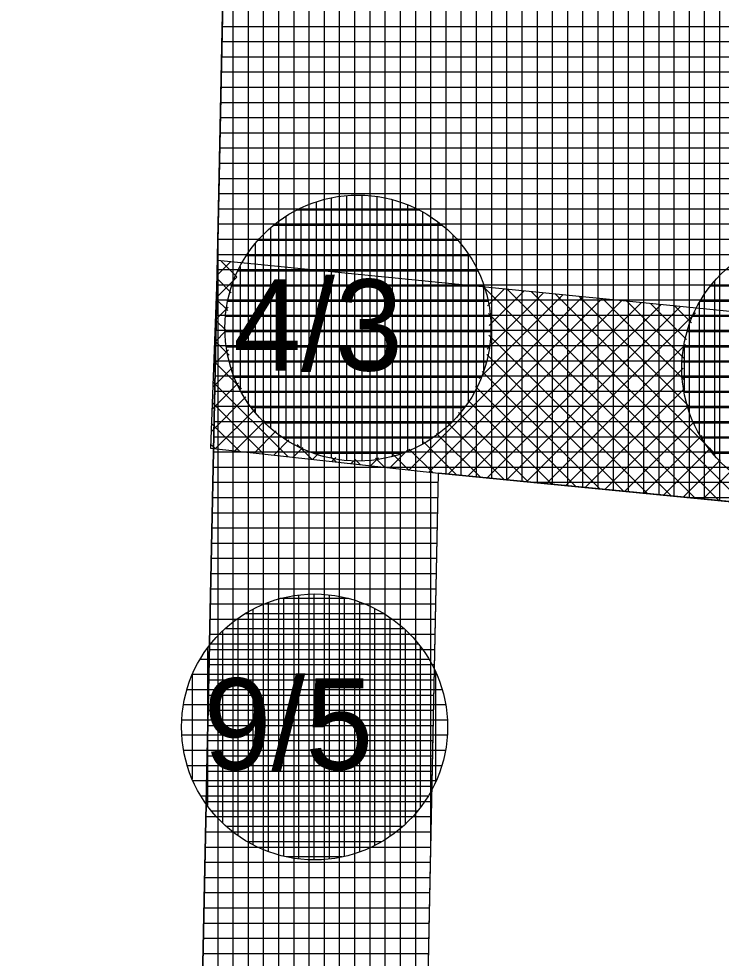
# Model space of a CAD drawing. Extents: x -566461 to -565198, y -1096301 to -1095707.
# Drawn here: x -565645.08 to -565635.84, y -1095892.27 to -1095879.91 of the extents above; entities that cross this region are included whole.
import ezdxf

# ---------------------------------------------------------------- set-up
doc = ezdxf.new("R2010")
doc.units = 0
for name, color, linetype in [('Vrstva 1', 7, 'Continuous'), ('Vrstva 40', 7, 'Continuous'), ('Vrstva 41', 7, 'Continuous'), ('Vrstva 42', 7, 'Continuous'), ('Vrstva 43', 7, 'Continuous'), ('Vrstva 44', 7, 'Continuous')]:
    doc.layers.add(name, color=color, linetype=linetype)

msp = doc.modelspace()

# ---------------------------------------------------------------- linework, layer by layer
at = {"layer": 'Vrstva 1'}
for p, q in [((-565642.52, -1095885.6), (-565642.21, -1095870.56)), ((-565645.08, -1096008.78), (-565642.52, -1095885.6)), ((-565642.11, -1096010.51), (-565639.56, -1095885.89)), ((-565630.78, -1095886.75), (-565639.56, -1095885.89))]:
    msp.add_line(p, q, dxfattribs=at)
at = {"layer": 'Vrstva 41'}
for p, q in [((-565642.475, -1095883.288), (-565642.297, -1095883.11)), ((-565642.212, -1095883.306), (-565642.42, -1095883.098)), ((-565642.486, -1095883.582), (-565642.214, -1095883.309)), ((-565642.285, -1095883.516), (-565642.477, -1095883.324)), ((-565638.97, -1095883.46), (-565638.953, -1095883.443)), ((-565636.186, -1095886.22), (-565638.965, -1095883.442)), ((-565639.944, -1095885.848), (-565637.667, -1095883.571)), ((-565639.024, -1095884.645), (-565637.924, -1095883.545)), ((-565638.918, -1095884.257), (-565638.182, -1095883.52)), ((-565638.916, -1095883.689), (-565638.696, -1095883.469)), ((-565638.892, -1095883.947), (-565638.439, -1095883.494)), ((-565635.873, -1095886.251), (-565638.651, -1095883.473)), ((-565635.559, -1095886.282), (-565638.337, -1095883.504)), ((-565635.93, -1095885.628), (-565638.023, -1095883.536)), ((-565636.267, -1095885.009), (-565637.708, -1095883.567)), ((-565642.497, -1095883.876), (-565642.326, -1095883.705)), ((-565642.333, -1095883.75), (-565642.487, -1095883.597)), ((-565639.689, -1095885.876), (-565637.41, -1095883.597)), ((-565639.433, -1095885.902), (-565637.153, -1095883.622)), ((-565639.175, -1095885.928), (-565636.895, -1095883.648)), ((-565638.918, -1095885.953), (-565636.638, -1095883.673)), ((-565638.66, -1095885.978), (-565636.381, -1095883.699)), ((-565636.334, -1095884.659), (-565637.394, -1095883.598)), ((-565636.335, -1095884.375), (-565637.08, -1095883.629)), ((-565636.298, -1095884.129), (-565636.766, -1095883.661)), ((-565636.233, -1095883.911), (-565636.452, -1095883.692)), ((-565636.5, -1095886.19), (-565638.901, -1095883.789)), ((-565638.402, -1095886.003), (-565636.179, -1095883.78)), ((-565642.348, -1095884.018), (-565642.497, -1095883.87)), ((-565642.508, -1095884.169), (-565642.349, -1095884.01)), ((-565636.813, -1095886.159), (-565638.9, -1095884.073)), ((-565642.314, -1095884.336), (-565642.507, -1095884.142)), ((-565638.145, -1095886.029), (-565636.311, -1095884.195)), ((-565642.519, -1095884.463), (-565642.324, -1095884.268)), ((-565642.152, -1095884.78), (-565642.517, -1095884.415)), ((-565637.127, -1095886.128), (-565638.926, -1095884.329)), ((-565642.53, -1095884.757), (-565642.271, -1095884.498)), ((-565637.44, -1095886.098), (-565638.988, -1095884.55)), ((-565637.887, -1095886.054), (-565636.342, -1095884.509)), ((-565641.543, -1095885.672), (-565642.527, -1095884.688)), ((-565642.541, -1095885.051), (-565642.192, -1095884.702)), ((-565637.754, -1095886.067), (-565639.072, -1095884.749)), ((-565637.63, -1095886.079), (-565636.32, -1095884.769)), ((-565642.552, -1095885.345), (-565642.093, -1095884.885)), ((-565638.068, -1095886.036), (-565639.175, -1095884.928)), ((-565641.861, -1095885.637), (-565642.538, -1095884.96)), ((-565642.492, -1095885.567), (-565641.976, -1095885.051)), ((-565637.372, -1095886.104), (-565636.269, -1095885.001)), ((-565638.381, -1095886.005), (-565639.296, -1095885.091)), ((-565642.179, -1095885.602), (-565642.548, -1095885.233)), ((-565642.237, -1095885.596), (-565641.843, -1095885.201)), ((-565638.695, -1095885.975), (-565639.433, -1095885.237)), ((-565637.114, -1095886.13), (-565636.194, -1095885.209)), ((-565641.982, -1095885.624), (-565641.693, -1095885.334)), ((-565639.008, -1095885.944), (-565639.586, -1095885.366)), ((-565636.857, -1095886.155), (-565636.097, -1095885.395)), ((-565642.497, -1095885.567), (-565642.558, -1095885.506)), ((-565641.728, -1095885.652), (-565641.527, -1095885.451)), ((-565641.473, -1095885.68), (-565641.344, -1095885.551)), ((-565641.225, -1095885.707), (-565641.42, -1095885.512)), ((-565639.322, -1095885.913), (-565639.756, -1095885.479)), ((-565641.218, -1095885.708), (-565641.14, -1095885.63)), ((-565640.908, -1095885.742), (-565640.976, -1095885.674)), ((-565640.963, -1095885.736), (-565640.911, -1095885.684)), ((-565640.199, -1095885.82), (-565639.955, -1095885.576)), ((-565639.954, -1095885.847), (-565640.156, -1095885.645)), ((-565639.636, -1095885.882), (-565639.946, -1095885.572)), ((-565636.599, -1095886.18), (-565635.982, -1095885.563)), ((-565640.708, -1095885.764), (-565640.653, -1095885.708)), ((-565640.59, -1095885.777), (-565640.658, -1095885.708)), ((-565640.454, -1095885.792), (-565640.349, -1095885.687)), ((-565640.272, -1095885.812), (-565640.39, -1095885.693)), ((-565636.342, -1095886.205), (-565635.851, -1095885.715)), ((-565636.084, -1095886.23), (-565635.703, -1095885.85))]:
    msp.add_line(p, q, dxfattribs=at)
at = {"layer": 'Vrstva 42'}
msp.add_lwpolyline([(-565642.468, -1095883.093), (-565642.56, -1095885.56), (-565639.56, -1095885.89), (-565630.78, -1095886.75), (-565609.49, -1095886.27), (-565595.88, -1095884.74), (-565585.92, -1095883.62), (-565568.01, -1095880.69), (-565521.32, -1095878.21), (-565520.95, -1095875.75), (-565568.143, -1095878.194), (-565586.324, -1095881.153), (-565609.769, -1095883.786), (-565630.836, -1095884.251)], close=True, dxfattribs=at)
at = {"layer": 'Vrstva 43'}
for p, q in [((-565642.06, -1096008.067), (-565642.06, -1095870.575)), ((-565641.86, -1095998.292), (-565641.86, -1095870.594)), ((-565641.66, -1095988.518), (-565641.66, -1095870.614)), ((-565641.46, -1095978.744), (-565641.46, -1095870.633)), ((-565641.26, -1095968.97), (-565641.26, -1095870.653)), ((-565641.06, -1095959.196), (-565641.06, -1095870.672)), ((-565640.86, -1095949.422), (-565640.86, -1095870.692)), ((-565640.66, -1095939.648), (-565640.66, -1095870.711)), ((-565640.46, -1095929.874), (-565640.46, -1095870.731)), ((-565640.26, -1095920.099), (-565640.26, -1095870.75)), ((-565640.06, -1095910.325), (-565640.06, -1095870.77)), ((-565639.86, -1095900.551), (-565639.86, -1095870.789)), ((-565639.66, -1095890.777), (-565639.66, -1095870.809)), ((-565639.46, -1095885.9), (-565639.46, -1095870.828)), ((-565639.26, -1095885.919), (-565639.26, -1095870.848)), ((-565639.06, -1095885.939), (-565639.06, -1095870.867)), ((-565638.86, -1095885.959), (-565638.86, -1095870.887)), ((-565638.66, -1095885.978), (-565638.66, -1095870.906)), ((-565638.46, -1095885.998), (-565638.46, -1095870.926)), ((-565638.26, -1095886.017), (-565638.26, -1095870.945)), ((-565638.06, -1095886.037), (-565638.06, -1095870.965)), ((-565637.86, -1095886.057), (-565637.86, -1095870.984)), ((-565637.66, -1095886.076), (-565637.66, -1095871.004)), ((-565637.46, -1095886.096), (-565637.46, -1095871.024)), ((-565637.26, -1095886.115), (-565637.26, -1095871.043)), ((-565637.06, -1095886.135), (-565637.06, -1095871.063)), ((-565636.86, -1095886.154), (-565636.86, -1095871.082)), ((-565636.66, -1095886.174), (-565636.66, -1095871.102)), ((-565636.46, -1095886.194), (-565636.46, -1095871.121)), ((-565636.26, -1095886.213), (-565636.26, -1095871.141)), ((-565636.06, -1095886.233), (-565636.06, -1095871.16)), ((-565635.86, -1095886.252), (-565635.86, -1095871.18)), ((-565642.26, -1096010.423), (-565642.26, -1095872.986)), ((-565642.405, -1095880.01), (-565555.208, -1095880.01)), ((-565642.409, -1095880.21), (-565558.973, -1095880.21)), ((-565642.413, -1095880.41), (-565562.739, -1095880.41)), ((-565642.417, -1095880.61), (-565566.504, -1095880.61)), ((-565642.421, -1095880.81), (-565568.836, -1095880.81)), ((-565642.425, -1095881.01), (-565570.212, -1095881.01)), ((-565642.43, -1095881.21), (-565571.588, -1095881.21)), ((-565642.434, -1095881.41), (-565572.965, -1095881.41)), ((-565642.438, -1095881.61), (-565574.341, -1095881.61)), ((-565642.442, -1095881.81), (-565575.717, -1095881.81)), ((-565642.446, -1095882.01), (-565577.094, -1095882.01)), ((-565642.45, -1095882.21), (-565578.47, -1095882.21)), ((-565642.454, -1095882.41), (-565579.846, -1095882.41)), ((-565642.46, -1096010.306), (-565642.46, -1095882.689)), ((-565642.458, -1095882.61), (-565579.746, -1095882.61)), ((-565642.462, -1095882.81), (-565580.969, -1095882.81)), ((-565642.467, -1095883.01), (-565582.191, -1095883.01)), ((-565642.471, -1095883.21), (-565583.414, -1095883.21)), ((-565642.475, -1095883.41), (-565584.636, -1095883.41)), ((-565642.479, -1095883.61), (-565585.859, -1095883.61)), ((-565642.483, -1095883.81), (-565589.48, -1095883.81)), ((-565642.487, -1095884.01), (-565590.857, -1095884.01)), ((-565642.491, -1095884.21), (-565592.233, -1095884.21)), ((-565642.495, -1095884.41), (-565593.609, -1095884.41)), ((-565642.5, -1095884.61), (-565594.985, -1095884.61)), ((-565642.504, -1095884.81), (-565596.503, -1095884.81)), ((-565642.508, -1095885.01), (-565598.282, -1095885.01)), ((-565642.512, -1095885.21), (-565600.061, -1095885.21)), ((-565642.516, -1095885.41), (-565601.84, -1095885.41)), ((-565642.52, -1095885.61), (-565603.619, -1095885.61)), ((-565642.524, -1095885.81), (-565605.398, -1095885.81)), ((-565642.529, -1095886.01), (-565639.562, -1095886.01)), ((-565638.335, -1095886.01), (-565607.177, -1095886.01)), ((-565642.533, -1095886.21), (-565639.567, -1095886.21)), ((-565636.293, -1095886.21), (-565608.956, -1095886.21)), ((-565642.537, -1095886.41), (-565639.571, -1095886.41)), ((-565642.541, -1095886.61), (-565639.575, -1095886.61)), ((-565642.545, -1095886.81), (-565639.579, -1095886.81)), ((-565642.549, -1095887.01), (-565639.583, -1095887.01)), ((-565642.553, -1095887.21), (-565639.587, -1095887.21)), ((-565642.558, -1095887.41), (-565639.591, -1095887.41)), ((-565642.562, -1095887.61), (-565639.595, -1095887.61)), ((-565642.566, -1095887.81), (-565639.599, -1095887.81)), ((-565642.57, -1095888.01), (-565639.603, -1095888.01)), ((-565642.574, -1095888.21), (-565639.607, -1095888.21)), ((-565642.578, -1095888.41), (-565639.612, -1095888.41)), ((-565642.583, -1095888.61), (-565639.616, -1095888.61)), ((-565642.587, -1095888.81), (-565639.62, -1095888.81)), ((-565642.591, -1095889.01), (-565639.624, -1095889.01)), ((-565642.595, -1095889.21), (-565639.628, -1095889.21)), ((-565642.599, -1095889.41), (-565639.632, -1095889.41)), ((-565642.603, -1095889.61), (-565639.636, -1095889.61)), ((-565642.607, -1095889.81), (-565639.64, -1095889.81)), ((-565642.612, -1095890.01), (-565639.644, -1095890.01)), ((-565642.616, -1095890.21), (-565639.648, -1095890.21)), ((-565642.62, -1095890.41), (-565639.652, -1095890.41)), ((-565642.624, -1095890.61), (-565639.657, -1095890.61)), ((-565642.628, -1095890.81), (-565639.661, -1095890.81)), ((-565642.632, -1095891.01), (-565639.665, -1095891.01)), ((-565642.637, -1095891.21), (-565639.669, -1095891.21)), ((-565642.641, -1095891.41), (-565639.673, -1095891.41)), ((-565642.645, -1095891.61), (-565639.677, -1095891.61)), ((-565642.649, -1095891.81), (-565639.681, -1095891.81)), ((-565642.653, -1095892.01), (-565639.685, -1095892.01)), ((-565642.657, -1095892.21), (-565639.689, -1095892.21))]:
    msp.add_line(p, q, dxfattribs=at)
msp.add_lwpolyline([(-565639.56, -1095885.89), (-565630.78, -1095886.75), (-565609.49, -1095886.27), (-565595.88, -1095884.74), (-565585.92, -1095883.62), (-565568.01, -1095880.69), (-565521.32, -1095878.21), (-565519.36, -1095863.08), (-565522.03, -1095863.23), (-565569.62, -1095865.76), (-565587.97, -1095868.76), (-565610.5, -1095871.29), (-565630.22, -1095871.73), (-565642.21, -1095870.56), (-565642.52, -1095885.6), (-565645.08, -1096008.78), (-565642.11, -1096010.51)], close=True, dxfattribs=at)
at = {"layer": 'Vrstva 44'}
for p, q in [((-565641.17, -1095882.321), (-565641.17, -1095885.639)), ((-565640.97, -1095882.267), (-565640.97, -1095885.693)), ((-565640.77, -1095882.237), (-565640.77, -1095885.722)), ((-565640.57, -1095882.232), (-565640.57, -1095885.727)), ((-565640.37, -1095882.25), (-565640.37, -1095885.711)), ((-565640.17, -1095882.291), (-565640.17, -1095885.671)), ((-565639.809, -1095882.43), (-565641.43, -1095882.43)), ((-565641.37, -1095882.4), (-565641.37, -1095885.559)), ((-565639.97, -1095882.356), (-565639.97, -1095885.603)), ((-565639.77, -1095882.452), (-565639.77, -1095885.508)), ((-565641.57, -1095882.512), (-565641.57, -1095885.45)), ((-565639.57, -1095882.582), (-565639.57, -1095885.38)), ((-565641.77, -1095882.663), (-565641.77, -1095885.296)), ((-565639.507, -1095882.63), (-565641.731, -1095882.63)), ((-565639.303, -1095882.83), (-565641.938, -1095882.83)), ((-565639.37, -1095882.757), (-565639.37, -1095885.202)), ((-565641.97, -1095882.869), (-565641.97, -1095885.091)), ((-565639.152, -1095883.03), (-565642.087, -1095883.03)), ((-565639.17, -1095883.001), (-565639.17, -1095884.956)), ((-565642.17, -1095883.172), (-565642.17, -1095884.788)), ((-565639.041, -1095883.23), (-565642.201, -1095883.23)), ((-565638.959, -1095883.43), (-565642.28, -1095883.43)), ((-565638.97, -1095883.401), (-565638.97, -1095884.559)), ((-565633.235, -1095883.43), (-565635.985, -1095883.43)), ((-565635.93, -1095883.362), (-565635.93, -1095885.658)), ((-565638.907, -1095883.63), (-565642.333, -1095883.63)), ((-565636.13, -1095883.645), (-565636.13, -1095885.377)), ((-565633.099, -1095883.63), (-565636.122, -1095883.63)), ((-565638.878, -1095883.83), (-565642.362, -1095883.83)), ((-565632.998, -1095883.83), (-565636.22, -1095883.83)), ((-565638.873, -1095884.03), (-565642.368, -1095884.03)), ((-565632.929, -1095884.03), (-565636.291, -1095884.03)), ((-565636.33, -1095884.197), (-565636.33, -1095884.822)), ((-565638.889, -1095884.23), (-565642.352, -1095884.23)), ((-565632.884, -1095884.23), (-565636.337, -1095884.23)), ((-565638.929, -1095884.43), (-565642.309, -1095884.43)), ((-565632.863, -1095884.43), (-565636.357, -1095884.43)), ((-565638.997, -1095884.63), (-565642.243, -1095884.63)), ((-565632.864, -1095884.63), (-565636.354, -1095884.63)), ((-565639.093, -1095884.83), (-565642.149, -1095884.83)), ((-565632.891, -1095884.83), (-565636.328, -1095884.83)), ((-565639.22, -1095885.03), (-565642.018, -1095885.03)), ((-565632.941, -1095885.03), (-565636.279, -1095885.03)), ((-565639.398, -1095885.23), (-565641.844, -1095885.23)), ((-565633.017, -1095885.23), (-565636.205, -1095885.23)), ((-565639.644, -1095885.43), (-565641.597, -1095885.43)), ((-565633.122, -1095885.43), (-565636.096, -1095885.43)), ((-565640.04, -1095885.63), (-565641.197, -1095885.63)), ((-565633.268, -1095885.63), (-565635.953, -1095885.63)), ((-565641.6, -1095887.531), (-565641.6, -1095890.931)), ((-565641.4, -1095887.495), (-565641.4, -1095890.967)), ((-565641.2, -1095887.481), (-565641.2, -1095890.979)), ((-565641, -1095887.49), (-565641, -1095890.968)), ((-565640.8, -1095887.525), (-565640.8, -1095890.934)), ((-565641.8, -1095887.591), (-565641.8, -1095890.869)), ((-565640.743, -1095887.54), (-565641.641, -1095887.54)), ((-565640.6, -1095887.585), (-565640.6, -1095890.877)), ((-565640.276, -1095887.74), (-565642.107, -1095887.74)), ((-565642, -1095887.68), (-565642, -1095890.781)), ((-565640.4, -1095887.67), (-565640.4, -1095890.79)), ((-565642.2, -1095887.803), (-565642.2, -1095890.657)), ((-565640.2, -1095887.788), (-565640.2, -1095890.671)), ((-565642.4, -1095887.967), (-565642.4, -1095890.494)), ((-565640.01, -1095887.94), (-565642.371, -1095887.94)), ((-565640, -1095887.949), (-565640, -1095890.512)), ((-565639.823, -1095888.14), (-565642.557, -1095888.14)), ((-565642.6, -1095888.194), (-565642.6, -1095890.264)), ((-565639.8, -1095888.17), (-565639.8, -1095890.292)), ((-565639.685, -1095888.34), (-565642.697, -1095888.34)), ((-565639.6, -1095888.502), (-565639.6, -1095889.958)), ((-565642.8, -1095888.549), (-565642.8, -1095889.912)), ((-565639.582, -1095888.54), (-565642.796, -1095888.54)), ((-565639.512, -1095888.74), (-565642.868, -1095888.74)), ((-565639.466, -1095888.94), (-565642.915, -1095888.94)), ((-565639.444, -1095889.14), (-565642.937, -1095889.14)), ((-565639.444, -1095889.34), (-565642.935, -1095889.34)), ((-565639.469, -1095889.54), (-565642.91, -1095889.54)), ((-565639.518, -1095889.74), (-565642.862, -1095889.74)), ((-565639.592, -1095889.94), (-565642.789, -1095889.94)), ((-565639.695, -1095890.14), (-565642.683, -1095890.14)), ((-565639.84, -1095890.34), (-565642.541, -1095890.34)), ((-565640.031, -1095890.54), (-565642.347, -1095890.54)), ((-565640.308, -1095890.74), (-565642.071, -1095890.74)), ((-565640.827, -1095890.94), (-565641.56, -1095890.94))]:
    msp.add_line(p, q, dxfattribs=at)
for centre in [(-565640.62, -1095883.98), (-565634.61, -1095884.51), (-565641.19, -1095889.23)]:
    msp.add_circle(centre, 1.75, dxfattribs=at)

# ---------------------------------------------------------------- texts
at = {"layer": 'Vrstva 40'}
for s, p in [('4/3', (-565642.26, -1095884.54)), ('9/5', (-565642.65, -1095889.79))]:
    msp.add_text(s, height=1.2, dxfattribs=at).set_placement(p)

doc.saveas('drawing.dxf')
